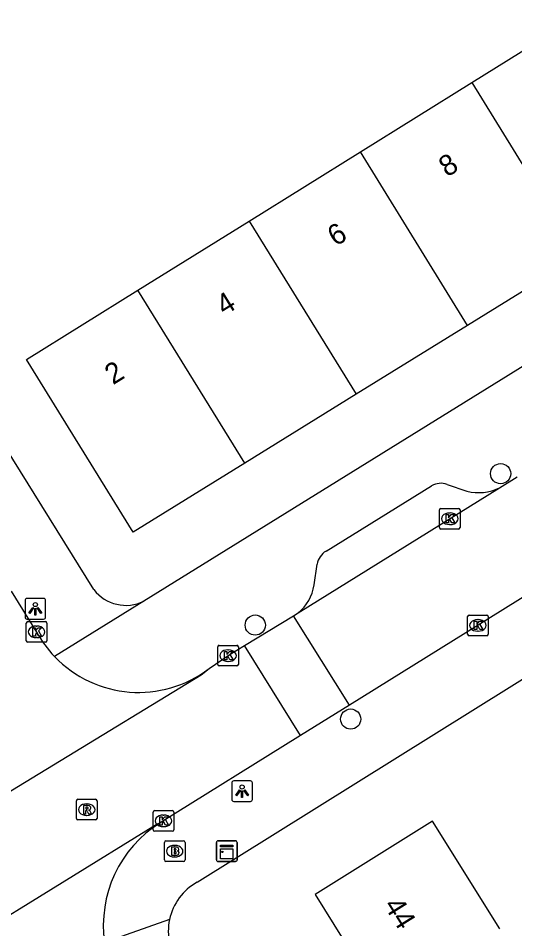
# Model space of a CAD drawing. Extents: x 160037 to 160839, y 385326 to 386441.
# Drawn here: x 160333.65 to 160357.7, y 386174.41 to 386218.54 of the extents above; entities that cross this region are included whole.
import ezdxf

# ---------------------------------------------------------------- set-up
doc = ezdxf.new("R2010")
doc.units = 0
for name, color, linetype in [('IMGEO_Boom', 7, 'Continuous'), ('IMGEO_Brandkraan', 7, 'Continuous'), ('IMGEO_Kast', 7, 'Continuous'), ('IMGEO_Kolk', 7, 'Continuous'), ('IMGEO_Lichtpunt', 7, 'Continuous'), ('IMGEO_Pand', 7, 'Continuous'), ('IMGEO_Pand_nummerreeks', 7, 'Continuous'), ('IMGEO_Rijbaan_lokaal_open', 7, 'Continuous'), ('IMGEO_Rioolput', 7, 'Continuous'), ('IMGEO_Voetpad_open', 7, 'Continuous')]:
    doc.layers.add(name, color=color, linetype=linetype)

msp = doc.modelspace()

# ---------------------------------------------------------------- linework, layer by layer
at = {"layer": 'IMGEO_Boom'}
for centre in [(160357.016, 386196.464), (160345.13, 386189.125), (160349.75, 386184.571)]:
    msp.add_circle(centre, 0.489, dxfattribs=at)
at = {"layer": 'IMGEO_Brandkraan'}
for p, q in [((160340.725, 386177.741), (160340.725, 386178.593)), ((160340.8, 386178.667), (160341.652, 386178.667)), ((160341.726, 386178.593), (160341.726, 386177.741)), ((160341.213, 386178.447), (160341.238, 386178.447)), ((160341.652, 386177.667), (160340.8, 386177.667)), ((160341.236, 386177.887), (160341.211, 386177.887))]:
    msp.add_line(p, q, dxfattribs=at)
for points in [[(160340.725, 386177.741), (160340.725, 386178.593)], [(160340.8, 386178.667), (160341.652, 386178.667)], [(160341.726, 386178.593), (160341.726, 386177.741)], [(160341.073, 386178.367), (160341.073, 386177.967), (160341.286, 386177.967)], [(160341.304, 386178.367), (160341.073, 386178.367)], [(160341.252, 386178.286), (160341.198, 386178.286), (160341.198, 386178.21)], [(160341.198, 386178.21), (160341.251, 386178.21)], [(160341.26, 386178.134), (160341.198, 386178.134), (160341.198, 386178.053)], [(160341.652, 386177.667), (160340.8, 386177.667)], [(160341.198, 386178.053), (160341.26, 386178.053)]]:
    msp.add_lwpolyline(points, dxfattribs=at)
for centre, radius, start, end in [((160340.802, 386178.591), 0.0765, 91.552, 178.448), ((160340.802, 386178.591), 0.0765, 91.552, 178.448), ((160341.65, 386178.591), 0.0765, 1.552, 88.448), ((160341.65, 386178.591), 0.0765, 1.552, 88.448), ((160341.253, 386178.248), 0.0379, 267.8285, 90.9355), ((160341.261, 386178.093), 0.0404, 269.8759, 90.5077), ((160341.308, 386178.222), 0.145, 59.4692, 91.5367), ((160341.333, 386178.269), 0.0922, 285.5137, 58.1501), ((160341.338, 386178.077), 0.105, 301.3115, 78.989), ((160340.802, 386177.743), 0.0765, 181.552, 268.448), ((160340.802, 386177.743), 0.0765, 181.552, 268.448), ((160341.292, 386178.218), 0.251, 268.6676, 293.5347), ((160341.65, 386177.743), 0.0765, 271.552, 358.448), ((160341.65, 386177.743), 0.0765, 271.552, 358.448)]:
    msp.add_arc(centre, radius, start, end, dxfattribs=at)
for centre, major_axis, ratio, start_param, end_param in [((160341.212, 386178.167), (-0.387, 0.002), 0.722429, 4.712389, 7.853982), ((160341.237, 386178.167), (-0.39, 0.002), 0.717154, 1.570796, 4.712389)]:
    msp.add_ellipse(centre, major_axis=major_axis, ratio=ratio, start_param=start_param, end_param=end_param, dxfattribs=at)
at = {"layer": 'IMGEO_Kast'}
for p, q in [((160343.251, 386177.744), (160343.251, 386178.585)), ((160343.251, 386178.585), (160343.251, 386177.744)), ((160343.326, 386178.669), (160344.167, 386178.669)), ((160344.167, 386178.669), (160343.326, 386178.669)), ((160344.251, 386178.594), (160344.251, 386177.753)), ((160344.251, 386177.753), (160344.251, 386178.594)), ((160344.176, 386177.669), (160343.335, 386177.669)), ((160343.335, 386177.669), (160344.176, 386177.669))]:
    msp.add_line(p, q, dxfattribs=at)
for points in [[(160343.446, 386178.459), (160344.046, 386178.459), (160344.046, 386178.374), (160343.446, 386178.374), (160343.446, 386178.459)], [(160343.446, 386178.284), (160344.046, 386178.284), (160344.046, 386177.795), (160343.446, 386177.795), (160343.446, 386178.284)]]:
    msp.add_lwpolyline(points, dxfattribs=at)
msp.add_circle((160343.53, 386178.133), 0.0377, dxfattribs=at)
for centre, start, end in [((160343.329, 386178.591), 92.4484, 184.2845), ((160343.329, 386178.591), 92.4484, 184.2845), ((160344.173, 386178.591), 2.4484, 94.2845), ((160344.173, 386178.591), 2.4484, 94.2845), ((160343.329, 386177.747), 182.4484, 274.2845), ((160343.329, 386177.747), 182.4484, 274.2845), ((160344.173, 386177.747), 272.4484, 4.2845), ((160344.173, 386177.747), 272.4484, 4.2845)]:
    msp.add_arc(centre, 0.0779, start, end, dxfattribs=at)
at = {"layer": 'IMGEO_Kolk'}
for p, q in [((160354.052, 386193.851), (160354.052, 386194.703)), ((160354.127, 386194.777), (160354.979, 386194.777)), ((160354.54, 386194.557), (160354.565, 386194.557)), ((160355.053, 386194.703), (160355.053, 386193.851)), ((160354.563, 386193.997), (160354.538, 386193.997)), ((160354.979, 386193.777), (160354.127, 386193.777)), ((160355.49, 386189.609), (160356.342, 386189.609)), ((160334.034, 386188.369), (160334.034, 386189.221)), ((160334.109, 386189.295), (160334.961, 386189.295)), ((160335.035, 386189.221), (160335.035, 386188.369)), ((160355.415, 386188.683), (160355.415, 386189.535)), ((160355.903, 386189.389), (160355.928, 386189.389)), ((160356.416, 386189.535), (160356.416, 386188.683)), ((160334.522, 386189.075), (160334.547, 386189.075)), ((160355.926, 386188.829), (160355.901, 386188.829)), ((160334.961, 386188.295), (160334.109, 386188.295)), ((160334.545, 386188.515), (160334.52, 386188.515)), ((160356.342, 386188.609), (160355.49, 386188.609)), ((160343.312, 386187.217), (160343.312, 386188.069)), ((160343.387, 386188.143), (160344.239, 386188.143)), ((160343.8, 386187.923), (160343.825, 386187.923)), ((160344.313, 386188.069), (160344.313, 386187.217)), ((160344.239, 386187.143), (160343.387, 386187.143)), ((160343.823, 386187.363), (160343.798, 386187.363)), ((160340.181, 386179.209), (160340.181, 386180.061)), ((160340.256, 386180.135), (160341.108, 386180.135)), ((160340.669, 386179.915), (160340.694, 386179.915)), ((160341.182, 386180.061), (160341.182, 386179.209)), ((160341.108, 386179.135), (160340.256, 386179.135)), ((160340.692, 386179.355), (160340.667, 386179.355))]:
    msp.add_line(p, q, dxfattribs=at)
for points in [[(160354.052, 386193.851), (160354.052, 386194.703)], [(160354.127, 386194.777), (160354.979, 386194.777)], [(160354.373, 386194.477), (160354.496, 386194.477), (160354.496, 386194.326), (160354.626, 386194.477), (160354.79, 386194.477), (160354.644, 386194.326), (160354.797, 386194.077), (160354.645, 386194.077), (160354.56, 386194.241), (160354.496, 386194.174), (160354.496, 386194.077), (160354.373, 386194.077), (160354.373, 386194.477)], [(160355.053, 386194.703), (160355.053, 386193.851)], [(160354.979, 386193.777), (160354.127, 386193.777)], [(160355.49, 386189.609), (160356.342, 386189.609)], [(160334.034, 386188.369), (160334.034, 386189.221)], [(160334.109, 386189.295), (160334.961, 386189.295)], [(160335.035, 386189.221), (160335.035, 386188.369)], [(160355.415, 386188.683), (160355.415, 386189.535)], [(160355.736, 386189.309), (160355.859, 386189.309), (160355.859, 386189.158), (160355.989, 386189.309), (160356.153, 386189.309), (160356.007, 386189.158), (160356.16, 386188.909), (160356.008, 386188.909), (160355.923, 386189.073), (160355.859, 386189.006), (160355.859, 386188.909), (160355.736, 386188.909), (160355.736, 386189.309)], [(160356.416, 386189.535), (160356.416, 386188.683)], [(160334.355, 386188.995), (160334.478, 386188.995), (160334.478, 386188.844), (160334.608, 386188.995), (160334.772, 386188.995), (160334.626, 386188.844), (160334.779, 386188.595), (160334.627, 386188.595), (160334.542, 386188.759), (160334.478, 386188.692), (160334.478, 386188.595), (160334.355, 386188.595), (160334.355, 386188.995)], [(160334.961, 386188.295), (160334.109, 386188.295)], [(160356.342, 386188.609), (160355.49, 386188.609)], [(160343.312, 386187.217), (160343.312, 386188.069)], [(160343.387, 386188.143), (160344.239, 386188.143)], [(160343.633, 386187.843), (160343.756, 386187.843), (160343.756, 386187.692), (160343.886, 386187.843), (160344.05, 386187.843), (160343.904, 386187.692), (160344.057, 386187.443), (160343.905, 386187.443), (160343.82, 386187.607), (160343.756, 386187.54), (160343.756, 386187.443), (160343.633, 386187.443), (160343.633, 386187.843)], [(160344.313, 386188.069), (160344.313, 386187.217)], [(160344.239, 386187.143), (160343.387, 386187.143)], [(160340.181, 386179.209), (160340.181, 386180.061)], [(160340.256, 386180.135), (160341.108, 386180.135)], [(160341.182, 386180.061), (160341.182, 386179.209)], [(160340.502, 386179.835), (160340.625, 386179.835), (160340.625, 386179.684), (160340.755, 386179.835), (160340.919, 386179.835), (160340.773, 386179.684), (160340.926, 386179.435), (160340.774, 386179.435), (160340.689, 386179.599), (160340.625, 386179.532), (160340.625, 386179.435), (160340.502, 386179.435), (160340.502, 386179.835)], [(160341.108, 386179.135), (160340.256, 386179.135)]]:
    msp.add_lwpolyline(points, dxfattribs=at)
for centre, start, end in [((160354.129, 386194.701), 91.552, 178.448), ((160354.129, 386194.701), 91.552, 178.448), ((160354.977, 386194.701), 1.552, 88.448), ((160354.977, 386194.701), 1.552, 88.448), ((160354.129, 386193.853), 181.552, 268.448), ((160354.129, 386193.853), 181.552, 268.448), ((160354.977, 386193.853), 271.552, 358.448), ((160354.977, 386193.853), 271.552, 358.448), ((160355.492, 386189.533), 91.552, 178.448), ((160355.492, 386189.533), 91.552, 178.448), ((160356.34, 386189.533), 1.552, 88.448), ((160356.34, 386189.533), 1.552, 88.448), ((160334.111, 386189.219), 91.552, 178.448), ((160334.111, 386189.219), 91.552, 178.448), ((160334.959, 386189.219), 1.552, 88.448), ((160334.959, 386189.219), 1.552, 88.448), ((160334.111, 386188.371), 181.552, 268.448), ((160334.111, 386188.371), 181.552, 268.448), ((160334.959, 386188.371), 271.552, 358.448), ((160334.959, 386188.371), 271.552, 358.448), ((160355.492, 386188.685), 181.552, 268.448), ((160355.492, 386188.685), 181.552, 268.448), ((160356.34, 386188.685), 271.552, 358.448), ((160356.34, 386188.685), 271.552, 358.448), ((160343.389, 386188.067), 91.552, 178.448), ((160343.389, 386188.067), 91.552, 178.448), ((160344.237, 386188.067), 1.552, 88.448), ((160344.237, 386188.067), 1.552, 88.448), ((160343.389, 386187.219), 181.552, 268.448), ((160343.389, 386187.219), 181.552, 268.448), ((160344.237, 386187.219), 271.552, 358.448), ((160344.237, 386187.219), 271.552, 358.448), ((160340.258, 386180.059), 91.552, 178.448), ((160340.258, 386180.059), 91.552, 178.448), ((160341.106, 386180.059), 1.552, 88.448), ((160341.106, 386180.059), 1.552, 88.448), ((160340.258, 386179.211), 181.552, 268.448), ((160340.258, 386179.211), 181.552, 268.448), ((160341.106, 386179.211), 271.552, 358.448), ((160341.106, 386179.211), 271.552, 358.448)]:
    msp.add_arc(centre, 0.0765, start, end, dxfattribs=at)
for centre, major_axis, ratio, start_param, end_param in [((160354.539, 386194.277), (-0.387, 0.002), 0.722429, 4.712389, 7.853982), ((160354.564, 386194.277), (-0.39, 0.002), 0.717154, 1.570796, 4.712389), ((160355.902, 386189.109), (-0.387, 0.002), 0.722429, 4.712389, 7.853982), ((160355.927, 386189.109), (-0.39, 0.002), 0.717154, 1.570796, 4.712389), ((160334.521, 386188.795), (-0.387, 0.002), 0.722429, 4.712389, 7.853982), ((160334.546, 386188.795), (-0.39, 0.002), 0.717154, 1.570796, 4.712389), ((160343.799, 386187.643), (-0.387, 0.002), 0.722429, 4.712389, 7.853982), ((160343.824, 386187.643), (-0.39, 0.002), 0.717154, 1.570796, 4.712389), ((160340.668, 386179.635), (-0.387, 0.002), 0.722429, 4.712389, 7.853982), ((160340.693, 386179.635), (-0.39, 0.002), 0.717154, 1.570796, 4.712389)]:
    msp.add_ellipse(centre, major_axis=major_axis, ratio=ratio, start_param=start_param, end_param=end_param, dxfattribs=at)
at = {"layer": 'IMGEO_Lichtpunt'}
for p, q in [((160333.976, 386190.319), (160333.976, 386189.512)), ((160333.976, 386190.319), (160333.976, 386189.512)), ((160334.878, 386190.414), (160334.07, 386190.414)), ((160334.878, 386190.414), (160334.07, 386190.414)), ((160334.972, 386189.512), (160334.972, 386190.319)), ((160334.972, 386189.512), (160334.972, 386190.319)), ((160334.07, 386189.418), (160334.878, 386189.418)), ((160334.07, 386189.418), (160334.878, 386189.418)), ((160343.993, 386181.479), (160343.993, 386180.672)), ((160343.993, 386181.479), (160343.993, 386180.672)), ((160344.895, 386181.574), (160344.087, 386181.574)), ((160344.895, 386181.574), (160344.087, 386181.574)), ((160344.989, 386180.672), (160344.989, 386181.479)), ((160344.989, 386180.672), (160344.989, 386181.479)), ((160344.087, 386180.578), (160344.895, 386180.578)), ((160344.087, 386180.578), (160344.895, 386180.578))]:
    msp.add_line(p, q, dxfattribs=at)
for points in [[(160334.35, 386189.983), (160334.389, 386189.955), (160334.201, 386189.693), (160334.163, 386189.72), (160334.35, 386189.983)], [(160334.452, 386189.935), (160334.499, 386189.935), (160334.499, 386189.613), (160334.452, 386189.613), (160334.452, 386189.935)], [(160334.562, 386189.955), (160334.6, 386189.982), (160334.787, 386189.72), (160334.748, 386189.692), (160334.562, 386189.955)], [(160344.367, 386181.143), (160344.406, 386181.115), (160344.218, 386180.853), (160344.18, 386180.88), (160344.367, 386181.143)], [(160344.469, 386181.095), (160344.516, 386181.095), (160344.516, 386180.773), (160344.469, 386180.773), (160344.469, 386181.095)], [(160344.579, 386181.115), (160344.617, 386181.142), (160344.804, 386180.88), (160344.765, 386180.852), (160344.579, 386181.115)]]:
    msp.add_lwpolyline(points, dxfattribs=at)
for centre in [(160334.475, 386190.117), (160344.492, 386181.277)]:
    msp.add_circle(centre, 0.0994, dxfattribs=at)
for centre, start, end in [((160334.07, 386190.319), 90, 180), ((160334.07, 386190.319), 90, 180), ((160334.878, 386190.319), 0, 90), ((160334.878, 386190.319), 0, 90), ((160334.07, 386189.512), 180, 270), ((160334.07, 386189.512), 180, 270), ((160334.878, 386189.512), 270, 0), ((160334.878, 386189.512), 270, 360), ((160344.087, 386181.479), 90, 180), ((160344.087, 386181.479), 90, 180), ((160344.895, 386181.479), 0, 90), ((160344.895, 386181.479), 0, 90), ((160344.087, 386180.672), 180, 270), ((160344.087, 386180.672), 180, 270), ((160344.895, 386180.672), 270, 0), ((160344.895, 386180.672), 270, 360)]:
    msp.add_arc(centre, 0.0946, start, end, dxfattribs=at)
at = {"layer": 'IMGEO_Pand'}
for points in [[(160355.614, 386215.415), (160361.006, 386218.769)], [(160350.222, 386212.061), (160355.614, 386215.415)], [(160355.614, 386215.415), (160360.818, 386206.994)], [(160344.83, 386208.707), (160350.222, 386212.061)], [(160355.418, 386203.651), (160350.222, 386212.061)], [(160339.438, 386205.353), (160344.83, 386208.707)], [(160344.83, 386208.707), (160350.019, 386200.309)], [(160360.818, 386206.994), (160355.418, 386203.651)], [(160344.62, 386196.966), (160339.221, 386193.624), (160334.046, 386201.999), (160339.438, 386205.353)], [(160344.62, 386196.966), (160339.438, 386205.353)], [(160355.418, 386203.651), (160350.019, 386200.309)], [(160350.019, 386200.309), (160344.62, 386196.966)], [(160356.97, 386174.4), (160353.721, 386179.618), (160348.03, 386176.074), (160351.279, 386170.856)]]:
    msp.add_lwpolyline(points, dxfattribs=at)
at = {"layer": 'IMGEO_Rijbaan_lokaal_open'}
for points in [[(160376.742, 386202.058), (160364.683, 386194.563), (160349.687, 386185.238)], [(160356.961, 386195.778), (160357.813, 386196.308)], [(160347.211, 386189.712), (160356.961, 386195.778)], [(160334.54, 386188.784), (160333.315, 386190.762)], [(160344.612, 386188.134), (160346.989, 386189.577)], [(160346.989, 386189.577), (160347.211, 386189.712)], [(160349.687, 386185.238), (160346.989, 386189.577)], [(160342.893, 386187.018), (160343.862, 386187.679), (160344.612, 386188.134)], [(160347.326, 386183.769), (160344.612, 386188.134)], [(160328.161, 386177.98), (160328.191, 386177.996), (160342.516, 386186.712), (160342.893, 386187.018)], [(160349.687, 386185.238), (160347.326, 386183.769)], [(160347.326, 386183.769), (160340.53, 386179.543)], [(160340.53, 386179.543), (160340.383, 386179.474), (160326.552, 386170.947), (160326.329, 386170.774)]]:
    msp.add_lwpolyline(points, dxfattribs=at)
for centre, radius, start, end in [((160339.521, 386191.525), 5.686, 208.8238, 223.6165), ((160339.476, 386191.492), 5.63, 223.693, 307.3727), ((160343.623, 386174.571), 5.855, 121.88, 188.137)]:
    msp.add_arc(centre, radius, start, end, dxfattribs=at)
at = {"layer": 'IMGEO_Rioolput'}
for p, q in [((160336.465, 386179.754), (160336.465, 386180.606)), ((160336.54, 386180.68), (160337.392, 386180.68)), ((160336.953, 386180.46), (160336.978, 386180.46)), ((160337.466, 386180.606), (160337.466, 386179.754)), ((160336.976, 386179.9), (160336.951, 386179.9)), ((160337.392, 386179.68), (160336.54, 386179.68))]:
    msp.add_line(p, q, dxfattribs=at)
for points in [[(160336.465, 386179.754), (160336.465, 386180.606)], [(160336.54, 386180.68), (160337.392, 386180.68)], [(160337.054, 386180.378), (160336.802, 386180.38), (160336.802, 386179.98)], [(160337.466, 386180.606), (160337.466, 386179.754)], [(160336.802, 386179.98), (160336.926, 386179.98), (160336.926, 386180.142), (160336.937, 386180.142)], [(160336.98, 386180.299), (160336.926, 386180.299), (160336.926, 386180.218)], [(160336.926, 386180.218), (160336.978, 386180.218)], [(160336.984, 386180.113), (160337.055, 386179.98), (160337.195, 386179.98), (160337.13, 386180.106)], [(160337.392, 386179.68), (160336.54, 386179.68)]]:
    msp.add_lwpolyline(points, dxfattribs=at)
for centre, radius, start, end in [((160336.542, 386180.604), 0.0765, 91.552, 178.448), ((160336.542, 386180.604), 0.0765, 91.552, 178.448), ((160337.053, 386180.268), 0.109, 350.3612, 89.416), ((160337.39, 386180.604), 0.0765, 1.552, 88.448), ((160337.39, 386180.604), 0.0765, 1.552, 88.448), ((160336.936, 386180.089), 0.0533, 26.0293, 88.6989), ((160336.962, 386180.407), 0.19, 274.7715, 282.9687), ((160336.986, 386180.203), 0.0964, 77.0061, 93.1865), ((160337, 386180.26), 0.0378, 276.6634, 79.6772), ((160337.051, 386180.268), 0.112, 277.5842, 350.9817), ((160337.035, 386180.053), 0.108, 29.5134, 73.7905), ((160336.542, 386179.756), 0.0765, 181.552, 268.448), ((160336.542, 386179.756), 0.0765, 181.552, 268.448), ((160337.39, 386179.756), 0.0765, 271.552, 358.448), ((160337.39, 386179.756), 0.0765, 271.552, 358.448)]:
    msp.add_arc(centre, radius, start, end, dxfattribs=at)
for centre, major_axis, ratio, start_param, end_param in [((160336.952, 386180.18), (-0.387, 0.002), 0.722429, 4.712389, 7.853982), ((160336.977, 386180.18), (-0.39, 0.002), 0.717154, 1.570796, 4.712389)]:
    msp.add_ellipse(centre, major_axis=major_axis, ratio=ratio, start_param=start_param, end_param=end_param, dxfattribs=at)
at = {"layer": 'IMGEO_Voetpad_open'}
for points in [[(160337.312, 386190.843), (160304.123, 386244.251)], [(160379.488, 386214.921), (160339.732, 386190.285)], [(160348.557, 386192.714), (160353.674, 386195.867)], [(160354.432, 386195.94), (160355.383, 386195.616)], [(160347.979, 386191.068), (160348.13, 386192.073)], [(160342.312, 386176.669), (160365.243, 386190.979)], [(160339.732, 386190.285), (160335.405, 386187.603)], [(160340.977, 386174.852), (160337.826, 386173.742)]]:
    msp.add_lwpolyline(points, dxfattribs=at)
for centre, radius, start, end in [((160354.127, 386195.137), 0.859, 69.2007, 121.8012), ((160355.954, 386197.817), 2.274, 255.4504, 296.2727), ((160349.034, 386191.933), 0.915, 121.4347, 171.2265), ((160345.866, 386191.369), 2.134, 309.0566, 351.8915), ((160338.862, 386192.038), 1.957, 217.6332, 296.3983), ((160343.671, 386174.271), 2.756, 119.5495, 167.839), ((160343.675, 386174.271), 2.76, 167.8455, 216.0601)]:
    msp.add_arc(centre, radius, start, end, dxfattribs=at)

# ---------------------------------------------------------------- texts
at = {"layer": 'IMGEO_Pand_nummerreeks'}
for s, rotation, p in [('8', 31.8828, (160354.422, 386210.811)), ('6', 31.8828, (160349.028, 386207.455)), ('4', 31.8828, (160343.636, 386204.101)), ('2', 31.8828, (160338.238, 386200.744)), ('44', 301.9103, (160351.326, 386175.548))]:
    msp.add_text(s, height=1, rotation=rotation, dxfattribs=at).set_placement(p)

doc.saveas('drawing.dxf')
